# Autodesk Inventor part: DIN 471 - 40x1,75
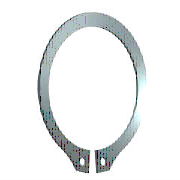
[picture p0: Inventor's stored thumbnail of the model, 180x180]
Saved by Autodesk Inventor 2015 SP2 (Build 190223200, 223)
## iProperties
IsCustomPart: 0
Created: 2012-02
Part Number: DIN 471 - 40x1,75
Material: Stahl, weich
Description: Sicherungsringe für Wellen
Document SubType Name: Modeling
Standard: DIN 471
Designer: Dan
Standards Organization: DIN
Language: de-DE
Size Designation: 40x1,75
Categories: <MemberInstance><Categories><Category DisplayName="Wellenteile" InternalName="7f7aeb1f-a693-4053-b835-cee3144e0d98" Mnemonic="SHFT"><Category DisplayName="Siche
Density: 7.85 g/cm^3
Appearance: Halbpoliert
Author: Dan
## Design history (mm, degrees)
node "WorkPlane1"
workplane "Work Plane2"
node "WorkPlane2"
node "WorkPoint1"
node "WorkAxis1"
body "Solid1"
node "Skizze1"
sketch "Skizze2"
  geometry: L1 (6.25, -23.827)-(6.25, -19.841); L2 (1.25, -24.708)-(6.25, -23.827); L3 (1.25, -18.708)-(1.25, -24.708); L4 (-1.25, -18.708)-(-1.25, -24.708); L5 (-1.25, -24.708)-(-6.25, -23.827); L6 (-6.25, -23.827)-(-6.25, -19.841); A1 r 18.75 centre (0, 0) between (1.25, -18.708) and (-1.25, -18.708); A2 r 21.95 centre (0, 1.2) between (6.25, -19.841) and (-6.25, -19.841); 1 further point
  constraints: 12 end point, 4 point on circle, 4 vertical, 2 centre point
  dimensions: "d2" = 18.75 radius of A1 (= 0.5 x Diam2); "d4" = 21.95 radius of A2 (= 0.166667 x ParA + 0.5 x Diam2 + 0.5 x b); "d6" = 0 horizontal distance of A2.centre A1.centre; "d8" = 1.25 horizontal distance of L3.start A1.centre (= 0.5 x Diam5); "d10" = 1.25 horizontal distance of L4.start A1.centre (= 0.5 x Diam5); "d12" = 6 distance of L4.start L4.end (= ParA); "d14" = 6 distance of L3.start L2.start (= ParA); "d16" = 80 deg angle of L2 L3; "d18" = 80 deg angle of L4 L5; "d20" = 5 horizontal distance of L4.start L6.end (= 2 x Diam5); "d22" = 5 horizontal distance of L1.start L3.start (= 2 x Diam5); "d24" = 1.2 distance of A1.centre A2.centre (= -msp_r2 + 0.5 x Diam2 + b); "d52" = 0 distance of point (0, 0) A1.centre; "d53" = 0 distance of A1.centre point (0, 0)
extrude "Extrusion1" new body sketch "Skizze2" distance "d25" = 1.75 (= ParS); taper "d26" = 0 deg
sketch "Skizze3"
  geometry: L1 (-1.25, -18.708)-(-1.25, -24.708) reference; L2 (-1.25, -24.708)-(-6.25, -23.827) reference; 1 further point
  dimensions: "d30" = 2 distance from line of L1 point (-3.25, -21.614) (= 0.8 x Diam5); "d32" = 2.7 distance from line of L2 point (-3.25, -21.614) (= 0.45 x ParA)
hole "Bohrung1" sketch "Skizze3" diameter "d33" = 2.5 (= Diam5); stored, may be unused: countersink angle "d37" = 60 deg, drill point angle "d39" = 118 deg; dims "d34" = 6, "d35" = 4, "d36" = 2, "d38" = 8
sketch "Skizze4"
  geometry: L1 (1.25, -24.708)-(1.25, -18.708) reference; L2 (6.25, -23.827)-(1.25, -24.708) reference; 1 further point
  dimensions: "d41" = 2 distance from line of L1 point (3.25, -21.614) (= 0.8 x Diam5); "d43" = 2.7 distance from line of L2 point (3.25, -21.614) (= 0.45 x ParA)
hole "Bohrung2" sketch "Skizze4" diameter "d44" = 2.5 (= Diam5); stored, may be unused: countersink angle "d48" = 60 deg, drill point angle "d50" = 118 deg; dims "d45" = 6, "d46" = 4, "d47" = 2, "d49" = 8
fillet "Rundung1" dims "d51" = 3.75 (= 1.5 x Diam5)
other parameters: "Diam5" = 2.5 [user parameter; used in 9 equation terms], "ParA" = 6 [user parameter; used in 6 equation terms], "b" = 4.4 [user parameter; used in 3 equation terms], "ParS" = 1.75 [user parameter; used in 2 equation terms], "Diam2" = 37.5 [user parameter; used in 4 equation terms], "msp_r2" = 21.95 (= 0.166667 x ParA + 0.5 x Diam2 + 0.5 x b) [user parameter; used in 1 equation term], "d0" = -1.75 (computed from ParS), "d1" = 14.3 (derived), "d3" = 0, "d5" = 0 (derived), "d7" = 1 (derived), "d9" = 1 (derived), "d11" = 4.8 (derived), "d13" = 4.8 (derived), "d15" = 80 deg (derived), "d17" = 80 deg (derived), "d19" = 4 (derived), "d21" = 4 (derived), "d23" = 0.95 (derived), "d27" = 0, "d28" = 0, "d29" = 1.6 (derived), "d31" = 2.16 (derived), "d40" = 1.6 (derived), "d42" = 2.16 (derived), "d55" = 0, "d56" = 0, "d57" = 0, "d58" = 0, "TEMPLATE" = 12.345 [user parameter]
